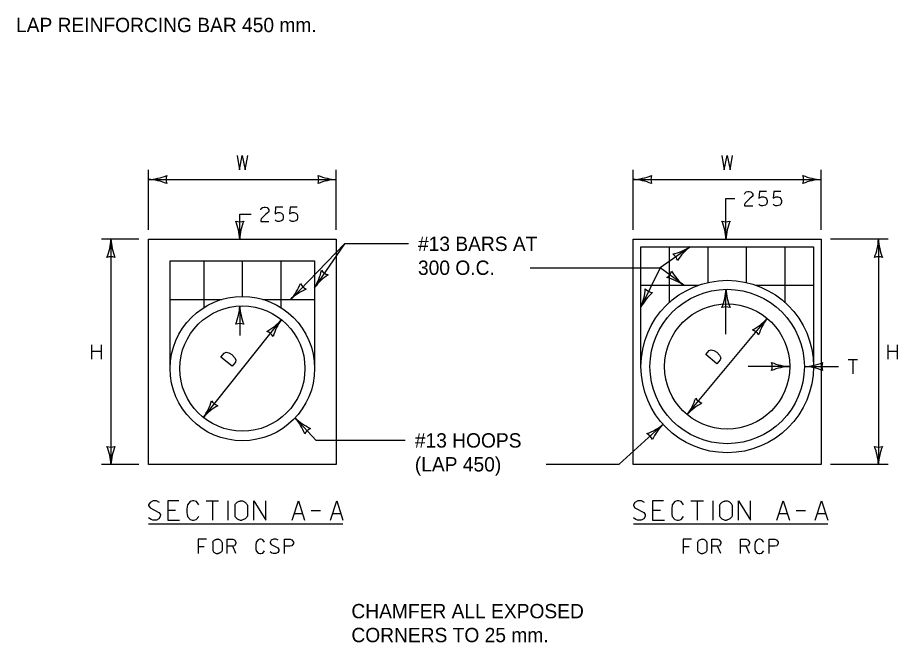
# Model space of a CAD drawing. Extents: x 49991.4 to 50043, y 49987.6 to 50011.4.
# Drawn here: x 50038.48 to 50042.158, y 49993.582 to 49996.195 of the extents above; entities that cross this region are included whole.
import ezdxf

# ---------------------------------------------------------------- set-up
doc = ezdxf.new("R2010")
doc.units = 0
for name, color, linetype in [('Level 1', 7, 'Continuous'), ('Level 2', 7, 'Continuous'), ('Level 3', 7, 'Continuous')]:
    doc.layers.add(name, color=color, linetype=linetype)

msp = doc.modelspace()

# ---------------------------------------------------------------- linework, layer by layer
at = {"layer": 'Level 1'}
for p, q in [((50039.0269, 49995.2678), (50039.8121, 49995.2678)), ((50039.0269, 49994.3256), (50039.0269, 49995.2678)), ((50039.8121, 49995.2678), (50039.8121, 49994.3256)), ((50041.054, 49995.2678), (50041.8391, 49995.2678)), ((50041.054, 49994.3256), (50041.054, 49995.2678)), ((50041.8391, 49995.2678), (50041.8391, 49994.3256)), ((50041.0859, 49995.236), (50041.8073, 49995.236)), ((50041.0859, 49994.7356), (50041.0859, 49995.236)), ((50041.2047, 49995.236), (50041.2047, 49995.0032)), ((50041.3655, 49995.236), (50041.3655, 49995.0871)), ((50041.5263, 49995.236), (50041.5263, 49995.0874)), ((50041.687, 49995.236), (50041.687, 49995.0045)), ((50041.8073, 49995.236), (50041.8073, 49994.7356)), ((50039.1176, 49995.1771), (50039.7214, 49995.1771)), ((50039.1176, 49994.727), (50039.1176, 49995.1771)), ((50039.2587, 49995.1771), (50039.2587, 49994.9825)), ((50039.4195, 49995.0289), (50039.4195, 49995.1771)), ((50039.5803, 49995.1771), (50039.5803, 49994.9825)), ((50039.7214, 49995.1771), (50039.7215, 49994.727)), ((50041.0859, 49995.0752), (50041.3251, 49995.0752)), ((50041.5682, 49995.0752), (50041.8073, 49995.0752)), ((50039.1176, 49995.0164), (50039.3335, 49995.0164)), ((50039.5055, 49995.0164), (50039.7214, 49995.0164)), ((50039.8121, 49994.3256), (50039.0269, 49994.3256)), ((50041.8391, 49994.3256), (50041.054, 49994.3256))]:
    msp.add_line(p, q, dxfattribs=at)
for centre, radius in [((50041.4466, 49994.7356), 0.3607), ((50041.4466, 49994.7356), 0.3228), ((50039.4195, 49994.727), 0.3019), ((50039.4195, 49994.727), 0.2617), ((50041.4466, 49994.7356), 0.2617)]:
    msp.add_circle(centre, radius, dxfattribs=at)
at = {"layer": 'Level 2'}
for p, q in [((50038.7906, 49994.7667), (50038.7906, 49994.8267)), ((50038.8299, 49994.7667), (50038.8299, 49994.8267)), ((50042.1191, 49994.7667), (50042.1191, 49994.8267)), ((50042.1584, 49994.7667), (50042.1584, 49994.8267)), ((50038.8299, 49994.7979), (50038.7906, 49994.7979)), ((50042.1584, 49994.7979), (50042.1191, 49994.7979)), ((50041.9521, 49994.7656), (50041.9913, 49994.7656)), ((50041.9719, 49994.7656), (50041.9719, 49994.7056)), ((50039.2675, 49994.1733), (50039.3198, 49994.1733)), ((50039.294, 49994.1733), (50039.294, 49994.0933)), ((50039.3604, 49994.0933), (50039.3604, 49994.1733)), ((50039.3875, 49994.1556), (50039.3875, 49994.1096)), ((50039.4108, 49994.1733), (50039.4171, 49994.1733)), ((50039.4404, 49994.1556), (50039.4404, 49994.1096)), ((50041.2946, 49994.1733), (50041.3469, 49994.1733)), ((50041.3211, 49994.1733), (50041.3211, 49994.0933)), ((50041.3875, 49994.0933), (50041.3875, 49994.1733)), ((50041.4146, 49994.1556), (50041.4146, 49994.1096)), ((50041.4379, 49994.1733), (50041.4442, 49994.1733)), ((50041.4675, 49994.1556), (50041.4675, 49994.1096)), ((50039.1403, 49994.1336), (50039.1075, 49994.1336)), ((50039.6364, 49994.1204), (50039.671, 49994.1204)), ((50039.7075, 49994.1336), (50039.7466, 49994.1336)), ((50039.7964, 49994.1204), (50039.831, 49994.1204)), ((50041.1674, 49994.1336), (50041.1346, 49994.1336)), ((50041.6635, 49994.1204), (50041.6981, 49994.1204)), ((50041.7346, 49994.1336), (50041.7737, 49994.1336)), ((50041.8235, 49994.1204), (50041.8581, 49994.1204)), ((50039.4108, 49994.0933), (50039.4171, 49994.0933)), ((50041.4379, 49994.0933), (50041.4442, 49994.0933)), ((50039.0275, 49994.0773), (50039.8398, 49994.0773)), ((50041.0546, 49994.0773), (50041.8669, 49994.0773)), ((50039.3127, 49994.0133), (50039.3175, 49994.0133)), ((50041.3398, 49994.0133), (50041.3446, 49994.0133)), ((50039.2357, 49993.9836), (50039.2603, 49993.9836)), ((50039.2952, 49994.0001), (50039.2952, 49993.9656)), ((50039.3349, 49994.0001), (50039.3349, 49993.9656)), ((50039.3926, 49993.9533), (50039.3789, 49993.984)), ((50041.2628, 49993.9836), (50041.2874, 49993.9836)), ((50041.3223, 49994.0001), (50041.3223, 49993.9656)), ((50041.362, 49994.0001), (50041.362, 49993.9656)), ((50041.4197, 49993.9533), (50041.406, 49993.984)), ((50041.5397, 49993.9533), (50041.526, 49993.984)), ((50039.3127, 49993.9533), (50039.3175, 49993.9533)), ((50041.3398, 49993.9533), (50041.3446, 49993.9533))]:
    msp.add_line(p, q, dxfattribs=at)
for points in [[(50039.3973, 49995.6176), (50039.4068, 49995.5576), (50039.4191, 49995.6176), (50039.4314, 49995.5576), (50039.4418, 49995.6176)], [(50041.4244, 49995.6176), (50041.4338, 49995.5576), (50041.4461, 49995.6176), (50041.4584, 49995.5576), (50041.4688, 49995.6176)], [(50041.5192, 49995.4558), (50041.5211, 49995.4615), (50041.5263, 49995.4662), (50041.5334, 49995.4681), (50041.5386, 49995.4681), (50041.5457, 49995.4662), (50041.5509, 49995.461), (50041.5533, 49995.4558), (50041.5533, 49995.4506), (50041.5514, 49995.4464), (50041.5396, 49995.4374), (50041.5211, 49995.4185), (50041.5192, 49995.4138), (50041.5192, 49995.4081), (50041.5533, 49995.4081)], [(50041.6109, 49995.4681), (50041.5816, 49995.4681), (50041.5792, 49995.4397), (50041.5906, 49995.4449), (50041.5986, 49995.4449), (50041.6062, 49995.4421), (50041.6109, 49995.4369), (50041.6133, 49995.4298), (50041.6133, 49995.4223), (50041.6109, 49995.4147), (50041.6062, 49995.41), (50041.5958, 49995.4081), (50041.5887, 49995.4081), (50041.5835, 49995.41), (50041.5792, 49995.4152)], [(50041.6709, 49995.4681), (50041.6416, 49995.4681), (50041.6392, 49995.4397), (50041.6506, 49995.4449), (50041.6586, 49995.4449), (50041.6662, 49995.4421), (50041.6709, 49995.4369), (50041.6733, 49995.4298), (50041.6733, 49995.4223), (50041.6709, 49995.4147), (50041.6662, 49995.41), (50041.6558, 49995.4081), (50041.6487, 49995.4081), (50041.6435, 49995.41), (50041.6392, 49995.4152)], [(50039.4962, 49995.3902), (50039.4981, 49995.3959), (50039.5033, 49995.4006), (50039.5104, 49995.4025), (50039.5156, 49995.4025), (50039.5227, 49995.4006), (50039.5279, 49995.3954), (50039.5303, 49995.3902), (50039.5303, 49995.385), (50039.5284, 49995.3808), (50039.5166, 49995.3718), (50039.4981, 49995.3529), (50039.4962, 49995.3482), (50039.4962, 49995.3425), (50039.5303, 49995.3425)], [(50039.5879, 49995.4025), (50039.5586, 49995.4025), (50039.5562, 49995.3742), (50039.5676, 49995.3794), (50039.5756, 49995.3794), (50039.5832, 49995.3765), (50039.5879, 49995.3713), (50039.5903, 49995.3643), (50039.5903, 49995.3567), (50039.5879, 49995.3491), (50039.5832, 49995.3444), (50039.5728, 49995.3425), (50039.5657, 49995.3425), (50039.5605, 49995.3444), (50039.5562, 49995.3496)], [(50039.6479, 49995.4025), (50039.6186, 49995.4025), (50039.6162, 49995.3742), (50039.6276, 49995.3794), (50039.6356, 49995.3794), (50039.6432, 49995.3765), (50039.6479, 49995.3713), (50039.6503, 49995.3643), (50039.6503, 49995.3567), (50039.6479, 49995.3491), (50039.6432, 49995.3444), (50039.6328, 49995.3425), (50039.6257, 49995.3425), (50039.6205, 49995.3444), (50039.6162, 49995.3496)], [(50039.3297, 49994.7748), (50039.3433, 49994.7918), (50039.3516, 49994.7955), (50039.363, 49994.793), (50039.3752, 49994.7863), (50039.3867, 49994.7735), (50039.3916, 49994.763), (50039.3902, 49994.7544), (50039.3766, 49994.7374), (50039.3297, 49994.7748)], [(50041.3578, 49994.7853), (50041.3717, 49994.802), (50041.3801, 49994.8054), (50041.3914, 49994.8028), (50041.4035, 49994.7959), (50041.4147, 49994.7828), (50041.4194, 49994.7722), (50041.4178, 49994.7636), (50041.4039, 49994.7469), (50041.3578, 49994.7853)], [(50039.0735, 49994.1676), (50039.0609, 49994.1733), (50039.0464, 49994.1733), (50039.0332, 49994.1676), (50039.0275, 49994.1575), (50039.0275, 49994.1537), (50039.0338, 49994.1443), (50039.0704, 49994.1254), (50039.0767, 49994.1166), (50039.076, 49994.109), (50039.0704, 49994.0989), (50039.0597, 49994.0933), (50039.0445, 49994.0933), (50039.0376, 49994.0958), (50039.0275, 49994.1027)], [(50039.1535, 49994.1733), (50039.1075, 49994.1733), (50039.1075, 49994.0933), (50039.1567, 49994.0933)], [(50039.2373, 49994.1575), (50039.2272, 49994.1708), (50039.2171, 49994.1733), (50039.2102, 49994.1733), (50039.2008, 49994.1708), (50039.1901, 49994.1575), (50039.1875, 49994.1399), (50039.1875, 49994.1304), (50039.1875, 49994.1241), (50039.1882, 49994.1185), (50039.1901, 49994.1084), (50039.2008, 49994.0958), (50039.2102, 49994.0933), (50039.2159, 49994.0933), (50039.2266, 49994.0958), (50039.2373, 49994.1084)], [(50039.3875, 49994.1556), (50039.3891, 49994.1585), (50039.3909, 49994.1612), (50039.393, 49994.1637), (50039.3953, 49994.166), (50039.3979, 49994.168), (50039.4006, 49994.1697), (50039.4036, 49994.1712), (50039.4066, 49994.1723), (50039.4098, 49994.1731), (50039.4108, 49994.1733)], [(50039.4404, 49994.1556), (50039.4389, 49994.1585), (50039.4371, 49994.1612), (50039.435, 49994.1637), (50039.4327, 49994.166), (50039.4301, 49994.168), (50039.4274, 49994.1697), (50039.4244, 49994.1712), (50039.4214, 49994.1723), (50039.4182, 49994.1731), (50039.4171, 49994.1733)], [(50039.4675, 49994.0933), (50039.4675, 49994.1733), (50039.5173, 49994.0933), (50039.5173, 49994.1733)], [(50039.6275, 49994.0933), (50039.654, 49994.1733), (50039.6798, 49994.0933)], [(50039.7875, 49994.0933), (50039.814, 49994.1733), (50039.8398, 49994.0933)], [(50041.1006, 49994.1676), (50041.088, 49994.1733), (50041.0735, 49994.1733), (50041.0603, 49994.1676), (50041.0546, 49994.1575), (50041.0546, 49994.1537), (50041.0609, 49994.1443), (50041.0975, 49994.1254), (50041.1038, 49994.1166), (50041.1031, 49994.109), (50041.0975, 49994.0989), (50041.0868, 49994.0933), (50041.0716, 49994.0933), (50041.0647, 49994.0958), (50041.0546, 49994.1027)], [(50041.1806, 49994.1733), (50041.1346, 49994.1733), (50041.1346, 49994.0933), (50041.1838, 49994.0933)], [(50041.2644, 49994.1575), (50041.2543, 49994.1708), (50041.2442, 49994.1733), (50041.2373, 49994.1733), (50041.2279, 49994.1708), (50041.2172, 49994.1575), (50041.2146, 49994.1399), (50041.2146, 49994.1304), (50041.2146, 49994.1241), (50041.2153, 49994.1185), (50041.2172, 49994.1084), (50041.2279, 49994.0958), (50041.2373, 49994.0933), (50041.243, 49994.0933), (50041.2537, 49994.0958), (50041.2644, 49994.1084)], [(50041.4146, 49994.1556), (50041.4162, 49994.1585), (50041.418, 49994.1612), (50041.4201, 49994.1637), (50041.4224, 49994.166), (50041.425, 49994.168), (50041.4277, 49994.1697), (50041.4307, 49994.1712), (50041.4337, 49994.1723), (50041.4369, 49994.1731), (50041.4379, 49994.1733)], [(50041.4675, 49994.1556), (50041.466, 49994.1585), (50041.4642, 49994.1612), (50041.4621, 49994.1637), (50041.4598, 49994.166), (50041.4572, 49994.168), (50041.4545, 49994.1697), (50041.4515, 49994.1712), (50041.4485, 49994.1723), (50041.4453, 49994.1731), (50041.4442, 49994.1733)], [(50041.4946, 49994.0933), (50041.4946, 49994.1733), (50041.5444, 49994.0933), (50041.5444, 49994.1733)], [(50041.6546, 49994.0933), (50041.6811, 49994.1733), (50041.7069, 49994.0933)], [(50041.8146, 49994.0933), (50041.8411, 49994.1733), (50041.8669, 49994.0933)], [(50039.3875, 49994.1096), (50039.3895, 49994.1066), (50039.3918, 49994.1039), (50039.3944, 49994.1013), (50039.3972, 49994.0991), (50039.4002, 49994.0972), (50039.4034, 49994.0956), (50039.4068, 49994.0943), (50039.4103, 49994.0934), (50039.4108, 49994.0933)], [(50039.4404, 49994.1096), (50039.4385, 49994.1066), (50039.4362, 49994.1039), (50039.4336, 49994.1013), (50039.4308, 49994.0991), (50039.4278, 49994.0972), (50039.4246, 49994.0956), (50039.4212, 49994.0943), (50039.4177, 49994.0934), (50039.4171, 49994.0933)], [(50041.4146, 49994.1096), (50041.4166, 49994.1066), (50041.4189, 49994.1039), (50041.4215, 49994.1013), (50041.4243, 49994.0991), (50041.4273, 49994.0972), (50041.4305, 49994.0956), (50041.4339, 49994.0943), (50041.4374, 49994.0934), (50041.4379, 49994.0933)], [(50041.4675, 49994.1096), (50041.4656, 49994.1066), (50041.4633, 49994.1039), (50041.4607, 49994.1013), (50041.4579, 49994.0991), (50041.4549, 49994.0972), (50041.4517, 49994.0956), (50041.4483, 49994.0943), (50041.4448, 49994.0934), (50041.4442, 49994.0933)], [(50039.2697, 49994.0133), (50039.2352, 49994.0133), (50039.2352, 49993.9533)], [(50039.2952, 49994.0001), (50039.2964, 49994.0022), (50039.2977, 49994.0043), (50039.2993, 49994.0062), (50039.3011, 49994.0079), (50039.303, 49994.0094), (50039.3051, 49994.0107), (50039.3073, 49994.0117), (50039.3096, 49994.0126), (50039.3119, 49994.0132), (50039.3127, 49994.0133)], [(50039.3349, 49994.0001), (50039.3338, 49994.0022), (50039.3324, 49994.0043), (50039.3308, 49994.0062), (50039.3291, 49994.0079), (50039.3272, 49994.0094), (50039.3251, 49994.0107), (50039.3229, 49994.0117), (50039.3206, 49994.0126), (50039.3182, 49994.0132), (50039.3174, 49994.0133)], [(50039.3552, 49993.9533), (50039.3552, 49994.0133), (50039.3793, 49994.0133), (50039.3864, 49994.011), (50039.3926, 49994.0015), (50039.3926, 49993.9958), (50039.3869, 49993.9864), (50039.3793, 49993.984), (50039.3552, 49993.984)], [(50039.5126, 49994.0015), (50039.505, 49994.0114), (50039.4975, 49994.0133), (50039.4923, 49994.0133), (50039.4852, 49994.0114), (50039.4771, 49994.0015), (50039.4752, 49993.9883), (50039.4752, 49993.9812), (50039.4752, 49993.9765), (50039.4757, 49993.9722), (50039.4771, 49993.9647), (50039.4852, 49993.9552), (50039.4923, 49993.9533), (50039.4965, 49993.9533), (50039.5045, 49993.9552), (50039.5126, 49993.9647)], [(50039.5697, 49994.0091), (50039.5603, 49994.0133), (50039.5494, 49994.0133), (50039.5395, 49994.0091), (50039.5352, 49994.0015), (50039.5352, 49993.9987), (50039.54, 49993.9916), (50039.5674, 49993.9774), (50039.5721, 49993.9708), (50039.5716, 49993.9651), (50039.5674, 49993.9576), (50039.5593, 49993.9533), (50039.548, 49993.9533), (50039.5428, 49993.9552), (50039.5352, 49993.9604)], [(50039.5952, 49993.9533), (50039.5952, 49994.0133), (50039.6193, 49994.0133), (50039.6264, 49994.011), (50039.6326, 49994.0015), (50039.6326, 49993.9958), (50039.6269, 49993.9864), (50039.6193, 49993.984), (50039.5952, 49993.984)], [(50041.2968, 49994.0133), (50041.2623, 49994.0133), (50041.2623, 49993.9533)], [(50041.3223, 49994.0001), (50041.3235, 49994.0022), (50041.3248, 49994.0043), (50041.3264, 49994.0062), (50041.3282, 49994.0079), (50041.3301, 49994.0094), (50041.3322, 49994.0107), (50041.3344, 49994.0117), (50041.3367, 49994.0126), (50041.339, 49994.0132), (50041.3398, 49994.0133)], [(50041.362, 49994.0001), (50041.3609, 49994.0022), (50041.3595, 49994.0043), (50041.3579, 49994.0062), (50041.3562, 49994.0079), (50041.3543, 49994.0094), (50041.3522, 49994.0107), (50041.35, 49994.0117), (50041.3477, 49994.0126), (50041.3453, 49994.0132), (50041.3445, 49994.0133)], [(50041.3823, 49993.9533), (50041.3823, 49994.0133), (50041.4064, 49994.0133), (50041.4135, 49994.011), (50041.4197, 49994.0015), (50041.4197, 49993.9958), (50041.414, 49993.9864), (50041.4064, 49993.984), (50041.3823, 49993.984)], [(50041.5023, 49993.9533), (50041.5023, 49994.0133), (50041.5264, 49994.0133), (50041.5335, 49994.011), (50041.5397, 49994.0015), (50041.5397, 49993.9958), (50041.534, 49993.9864), (50041.5264, 49993.984), (50041.5023, 49993.984)], [(50041.5997, 49994.0015), (50041.5921, 49994.0114), (50041.5846, 49994.0133), (50041.5794, 49994.0133), (50041.5723, 49994.0114), (50041.5642, 49994.0015), (50041.5623, 49993.9883), (50041.5623, 49993.9812), (50041.5623, 49993.9765), (50041.5628, 49993.9722), (50041.5642, 49993.9647), (50041.5723, 49993.9552), (50041.5794, 49993.9533), (50041.5836, 49993.9533), (50041.5916, 49993.9552), (50041.5997, 49993.9647)], [(50041.6223, 49993.9533), (50041.6223, 49994.0133), (50041.6464, 49994.0133), (50041.6535, 49994.011), (50041.6597, 49994.0015), (50041.6597, 49993.9958), (50041.654, 49993.9864), (50041.6464, 49993.984), (50041.6223, 49993.984)], [(50039.2952, 49993.9656), (50039.2967, 49993.9633), (50039.2984, 49993.9613), (50039.3004, 49993.9594), (50039.3025, 49993.9577), (50039.3047, 49993.9562), (50039.3071, 49993.955), (50039.3097, 49993.9541), (50039.3123, 49993.9534), (50039.3127, 49993.9533)], [(50039.3349, 49993.9656), (50039.3334, 49993.9633), (50039.3317, 49993.9613), (50039.3298, 49993.9594), (50039.3277, 49993.9577), (50039.3254, 49993.9562), (50039.323, 49993.955), (50039.3205, 49993.9541), (50039.3179, 49993.9534), (50039.3174, 49993.9533)], [(50041.3223, 49993.9656), (50041.3238, 49993.9633), (50041.3255, 49993.9613), (50041.3275, 49993.9594), (50041.3296, 49993.9577), (50041.3318, 49993.9562), (50041.3342, 49993.955), (50041.3368, 49993.9541), (50041.3394, 49993.9534), (50041.3398, 49993.9533)], [(50041.362, 49993.9656), (50041.3605, 49993.9633), (50041.3588, 49993.9613), (50041.3569, 49993.9594), (50041.3548, 49993.9577), (50041.3525, 49993.9562), (50041.3501, 49993.955), (50041.3476, 49993.9541), (50041.345, 49993.9534), (50041.3445, 49993.9533)]]:
    msp.add_lwpolyline(points, dxfattribs=at)
at = {"layer": 'Level 3'}
for p, q in [((50039.0269, 49995.3078), (50039.0269, 49995.5576)), ((50039.8121, 49995.3078), (50039.8121, 49995.5576)), ((50041.054, 49995.3078), (50041.054, 49995.5576)), ((50041.8391, 49995.3078), (50041.8391, 49995.5576)), ((50039.0269, 49995.5176), (50039.8121, 49995.5176)), ((50041.054, 49995.5176), (50041.8391, 49995.5176)), ((50041.4415, 49995.2678), (50041.4415, 49995.4381)), ((50041.4415, 49995.4381), (50041.4792, 49995.4381)), ((50039.4084, 49995.2678), (50039.4084, 49995.3725)), ((50039.4084, 49995.3725), (50039.4562, 49995.3725)), ((50038.9869, 49995.2678), (50038.8298, 49995.2678)), ((50038.8698, 49995.2678), (50038.8698, 49994.3256)), ((50042.1191, 49995.2678), (50041.8791, 49995.2678)), ((50042.0791, 49995.2678), (50042.0791, 49994.3256)), ((50039.846, 49995.2487), (50039.6216, 49995.0164)), ((50039.846, 49995.2487), (50039.7214, 49995.0659)), ((50040.1137, 49995.2487), (50039.846, 49995.2487)), ((50041.2913, 49995.236), (50041.1667, 49995.1488)), ((50040.6233, 49995.1487), (50041.1667, 49995.1488)), ((50041.1667, 49995.1488), (50041.0859, 49994.9843)), ((50041.265, 49995.0752), (50041.1667, 49995.1488)), ((50041.4415, 49994.871), (50041.4415, 49995.0584)), ((50039.4084, 49994.9885), (50039.4084, 49994.8647)), ((50039.2563, 49994.5224), (50039.5827, 49994.9316)), ((50041.2792, 49994.5344), (50041.614, 49994.9368)), ((50041.7083, 49994.7356), (50041.5349, 49994.7356)), ((50041.7695, 49994.7356), (50041.9121, 49994.7356)), ((50039.7284, 49994.4266), (50039.6401, 49994.5209)), ((50040.9951, 49994.3266), (50041.1787, 49994.4941)), ((50040.1006, 49994.4266), (50039.7284, 49994.4266)), ((50038.9869, 49994.3256), (50038.8298, 49994.3256)), ((50040.6896, 49994.3266), (50040.9951, 49994.3266)), ((50042.1191, 49994.3256), (50041.8791, 49994.3256))]:
    msp.add_line(p, q, dxfattribs=at)
for centre, radius, start, end in [((50039.0155, 49995.7503), 0.233, 272.8273, 292.0772), ((50039.0178, 49995.2955), 0.2223, 67.456, 87.6395), ((50039.1552, 49995.5176), 0.0548, 162.1388, 197.8612), ((50039.8213, 49995.7398), 0.2223, 247.456, 267.6395), ((50039.6839, 49995.5176), 0.0548, 342.1388, 17.8612), ((50039.8236, 49995.2849), 0.233, 92.8273, 112.0772), ((50041.0426, 49995.7503), 0.233, 272.8273, 292.0772), ((50041.0449, 49995.2955), 0.2223, 67.456, 87.6395), ((50041.1823, 49995.5176), 0.0548, 162.1388, 197.8612), ((50041.8483, 49995.7398), 0.2223, 247.456, 267.6395), ((50041.7109, 49995.5176), 0.0548, 342.1388, 17.8612), ((50041.8506, 49995.2849), 0.233, 92.8273, 112.0772), ((50039.4084, 49995.396), 0.0548, 252.1388, 287.8612), ((50039.1757, 49995.2563), 0.233, 2.8273, 22.0772), ((50039.6306, 49995.2587), 0.2223, 157.456, 177.6395), ((50041.4415, 49995.396), 0.0548, 252.1388, 287.8612), ((50041.2088, 49995.2563), 0.233, 2.8273, 22.0772), ((50041.6637, 49995.2587), 0.2223, 157.456, 177.6395), ((50038.6477, 49995.277), 0.2223, 337.456, 357.6395), ((50039.1026, 49995.2793), 0.233, 182.8273, 202.0772), ((50041.857, 49995.277), 0.2223, 337.456, 357.6395), ((50042.3119, 49995.2793), 0.233, 182.8273, 202.0772), ((50041.1715, 49995.4233), 0.2223, 282.4274, 302.6109), ((50041.4341, 49995.0519), 0.233, 127.7987, 147.0485), ((50038.8698, 49995.1396), 0.0548, 72.1388, 107.8612), ((50041.1863, 49995.1625), 0.0548, 17.1102, 52.8325), ((50042.0791, 49995.1396), 0.0548, 72.1388, 107.8612), ((50039.5227, 49995.1875), 0.233, 328.555, 347.8049), ((50039.8999, 49994.9333), 0.2223, 123.1837, 143.3672), ((50039.7936, 49995.1719), 0.0548, 217.8665, 253.5889), ((50041.1624, 49995.152), 0.0548, 305.349, 341.0713), ((50041.4054, 49995.2476), 0.2223, 210.6662, 230.8497), ((50039.4463, 49995.1698), 0.233, 318.8188, 338.0686), ((50039.7107, 49995.1086), 0.0548, 208.1303, 243.8526), ((50041.1349, 49994.882), 0.233, 56.0375, 75.2873), ((50039.775, 49994.8555), 0.2223, 113.4475, 133.631), ((50040.8719, 49995.0765), 0.233, 336.6993, 355.9492), ((50041.2813, 49994.8783), 0.2223, 131.328, 151.5115), ((50041.1424, 49995.0994), 0.0548, 226.0108, 261.7332), ((50041.2194, 49995.0676), 0.2223, 337.456, 357.6395), ((50041.6743, 49995.0699), 0.233, 182.8273, 202.0772), ((50039.1863, 49994.9976), 0.2223, 337.456, 357.6395), ((50039.6412, 49995), 0.233, 182.8273, 202.0772), ((50041.4415, 49994.9302), 0.0548, 72.1388, 107.8612), ((50039.4148, 49995.0773), 0.2223, 298.8783, 319.0618), ((50039.7718, 49994.7955), 0.233, 144.2496, 163.4994), ((50041.449, 49995.0859), 0.2223, 297.7037, 317.8872), ((50041.8002, 49994.7969), 0.233, 143.075, 162.3249), ((50039.4084, 49994.8603), 0.0548, 72.1388, 107.8612), ((50041.532, 49994.8383), 0.0548, 32.3865, 68.1089), ((50039.5028, 49994.8314), 0.0548, 33.5611, 69.2834), ((50041.7175, 49994.9578), 0.2223, 247.456, 267.6395), ((50041.5801, 49994.7356), 0.0548, 342.1388, 17.8612), ((50041.7584, 49994.9684), 0.233, 272.7247, 291.9746), ((50041.8977, 49994.7354), 0.0548, 162.0362, 197.7586), ((50041.7198, 49994.5029), 0.233, 92.8273, 112.0772), ((50041.7599, 49994.5135), 0.2223, 67.3534, 87.5369), ((50041.093, 49994.6744), 0.233, 323.075, 342.3249), ((50041.3612, 49994.633), 0.0548, 212.3865, 248.1089), ((50039.0673, 49994.6586), 0.233, 324.2496, 343.4994), ((50039.4243, 49994.3768), 0.2223, 118.8783, 139.0618), ((50039.3363, 49994.6227), 0.0548, 213.5611, 249.2834), ((50041.4442, 49994.3853), 0.2223, 117.7037, 137.8872), ((50039.4718, 49994.3757), 0.2223, 20.5942, 40.7777), ((50039.8021, 49994.6884), 0.233, 225.9655, 245.2153), ((50041.0356, 49994.6643), 0.2223, 289.8633, 310.0468), ((50041.3441, 49994.3301), 0.233, 135.2346, 154.4844), ((50039.7278, 49994.4273), 0.0548, 115.277, 150.9993), ((50041.084, 49994.4077), 0.0548, 24.5461, 60.2684), ((50038.8698, 49994.4538), 0.0548, 252.1388, 287.8612), ((50038.6371, 49994.3141), 0.233, 2.8273, 22.0772), ((50039.092, 49994.3165), 0.2223, 157.456, 177.6395), ((50042.0791, 49994.4538), 0.0548, 252.1388, 287.8612), ((50041.8464, 49994.3141), 0.233, 2.8273, 22.0772), ((50042.3013, 49994.3165), 0.2223, 157.456, 177.6395)]:
    msp.add_arc(centre, radius, start, end, dxfattribs=at)

# ---------------------------------------------------------------- texts
at = {"layer": 'Level 2'}
for s, p in [('LAP REINFORCING BAR 450 mm.', (50038.4729, 49996.1338)), ('#13 BARS AT ', (50040.1537, 49995.2187)), ('300 O.C.', (50040.1537, 49995.1187)), ('#13 HOOPS', (50040.1406, 49994.3966)), ('(LAP 450)', (50040.1406, 49994.2966)), ('CHAMFER ALL EXPOSED', (50039.8753, 49993.6827)), ('CORNERS TO 25 mm.', (50039.8753, 49993.5827))]:
    msp.add_text(s, height=0.06, dxfattribs=at).set_placement(p)

doc.saveas('drawing.dxf')
